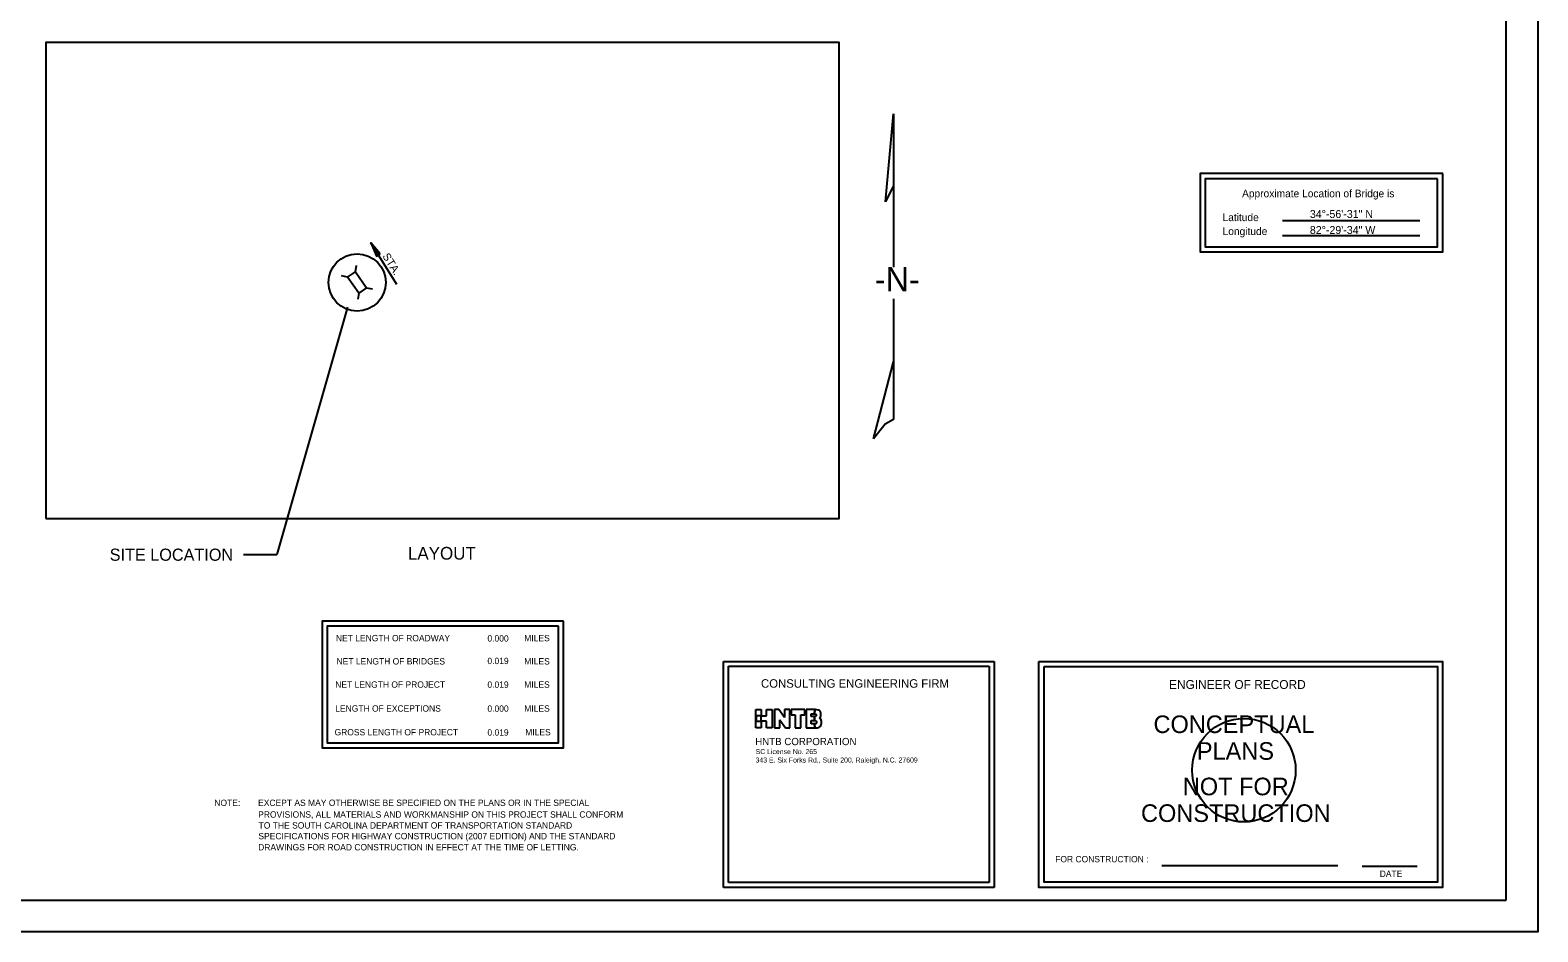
# Model space of a CAD drawing. Extents: x -2.83 to 3.9, y -2.5 to 2.32.
# Drawn here: x 1.021 to 3, y -2.5 to -1.316 of the extents above; entities that cross this region are included whole.
import ezdxf

# ---------------------------------------------------------------- set-up
doc = ezdxf.new("R2010")
doc.units = 0
for name, color, linetype in [('BR_AUTO DIMENSION', 7, 'Continuous'), ('BR_BORDER LINES', 7, 'Continuous'), ('BR_DETAILS', 7, 'Continuous'), ('BR_TEXT', 7, 'Continuous'), ('Default', 7, 'Continuous'), ('NoPlot', 7, 'Continuous'), ('V7_1', 7, 'Continuous'), ('V7_23', 7, 'Continuous')]:
    doc.layers.add(name, color=color, linetype=linetype)

msp = doc.modelspace()

# ---------------------------------------------------------------- linework, layer by layer
at = {"layer": 'BR_AUTO DIMENSION'}
for p, q in [((2.1436, -1.5418), (2.1542, -1.4259)), ((2.1542, -1.4259), (2.1542, -1.5203)), ((2.1542, -1.5203), (2.1436, -1.5418)), ((2.1542, -1.5203), (2.1542, -1.5857)), ((2.1542, -1.5857), (2.1542, -1.6274)), ((1.4372, -1.6798), (1.3443, -2.0048)), ((2.1542, -1.6691), (2.1542, -1.7516)), ((2.1279, -1.8526), (2.1542, -1.7516)), ((2.1542, -1.7516), (2.1542, -1.7641)), ((2.1542, -1.7641), (2.1542, -1.8273)), ((1.3005, -2.0048), (1.3443, -2.0048)), ((1.931, -2.1449), (2.286, -2.1449)), ((1.931, -2.4416), (1.931, -2.1449)), ((1.9373, -2.1513), (2.2796, -2.1513)), ((1.9373, -2.4352), (1.9373, -2.1513)), ((2.2796, -2.1513), (2.2796, -2.4352)), ((2.286, -2.1449), (2.286, -2.4416)), ((2.286, -2.4416), (1.931, -2.4416)), ((2.2796, -2.4352), (1.9373, -2.4352))]:
    msp.add_line(p, q, dxfattribs=at)
msp.add_lwpolyline([(2.1542, -1.8273), (2.1429, -1.8334), (2.1279, -1.8526)], dxfattribs=at)
msp.add_circle((1.4498, -1.6474), 0.0376, dxfattribs=at)
at = {"layer": 'BR_BORDER LINES'}
for p, q in [((2.9583, -2.4582), (2.9583, -0.7082)), ((2.9583, -1.3928), (2.9583, -0.8053)), ((0.1667, -2.4582), (2.9583, -2.4582))]:
    msp.add_line(p, q, dxfattribs=at)
msp.add_lwpolyline([(1.0411, -1.9573), (2.0828, -1.9573), (2.0828, -1.3323), (1.0411, -1.3323)], close=True, dxfattribs=at)
at = {"layer": 'BR_DETAILS'}
for p, q in [((2.6648, -1.5663), (2.8451, -1.5663)), ((2.6648, -1.5856), (2.8451, -1.5856)), ((2.5063, -2.4129), (2.7373, -2.4129)), ((2.7692, -2.4138), (2.8416, -2.4138))]:
    msp.add_line(p, q, dxfattribs=at)
for points in [[(2.8751, -1.5046), (2.5566, -1.5046), (2.5566, -1.6073), (2.8751, -1.6073)], [(2.8684, -1.5113), (2.5633, -1.5113), (2.5633, -1.6006), (2.8684, -1.6006)], [(2.345, -2.1449), (2.875, -2.1449), (2.875, -2.4416), (2.345, -2.4416)], [(2.3517, -2.1515), (2.8683, -2.1515), (2.8683, -2.4349), (2.3517, -2.4349)]]:
    msp.add_lwpolyline(points, close=True, dxfattribs=at)
at = {"layer": 'BR_TEXT'}
for p, q in [((1.5018, -1.6501), (1.4678, -1.5956)), ((1.4374, -1.6404), (1.4295, -1.6388)), ((1.4475, -1.6334), (1.4488, -1.6253)), ((1.4521, -1.6614), (1.4509, -1.6695)), ((1.4622, -1.6544), (1.4702, -1.656))]:
    msp.add_line(p, q, dxfattribs=at)
for points in [[(1.4801, -1.6099), (1.4678, -1.5956), (1.4753, -1.6129)], [(1.4374, -1.6404), (1.4475, -1.6334), (1.4622, -1.6544), (1.4521, -1.6614)], [(1.7207, -2.0919), (1.4041, -2.0919), (1.4041, -2.2586), (1.7207, -2.2586)], [(1.7141, -2.0986), (1.4107, -2.0986), (1.4107, -2.2519), (1.7141, -2.2519)]]:
    msp.add_lwpolyline(points, close=True, dxfattribs=at)
at = {"layer": 'Default'}
msp.add_line((2.61, -2.2932), (2.61, -2.2932), dxfattribs=at)
at = {"layer": 'NoPlot'}
msp.add_lwpolyline([(0, -0.6667), (3, -0.6667), (3, -2.5), (0, -2.5)], close=True, dxfattribs=at)
msp.add_circle((2.6141, -2.2878), 0.0679, dxfattribs=at)
at = {"layer": 'V7_23'}
for p, q in [((1.9733, -2.2323), (1.9733, -2.2083)), ((1.9733, -2.2083), (1.9804, -2.2083)), ((1.9804, -2.2164), (1.9736, -2.2164)), ((1.9736, -2.2164), (1.9736, -2.2235)), ((1.9804, -2.2083), (1.9804, -2.2164)), ((1.9804, -2.2235), (1.9804, -2.2164)), ((1.9804, -2.2164), (1.9875, -2.2164)), ((1.9875, -2.2164), (1.9875, -2.2083)), ((1.9875, -2.2083), (1.9946, -2.2083)), ((1.9946, -2.2083), (1.9946, -2.2323)), ((2.0037, -2.2083), (1.9978, -2.2083)), ((1.9978, -2.2083), (1.9978, -2.2323)), ((2.0108, -2.2188), (2.0037, -2.2083)), ((2.0178, -2.2083), (2.0108, -2.2083)), ((2.0108, -2.2083), (2.0108, -2.2188)), ((2.0178, -2.2323), (2.0178, -2.2083)), ((2.0198, -2.2083), (2.0198, -2.2153)), ((2.0375, -2.2083), (2.0198, -2.2083)), ((2.0198, -2.2153), (2.0251, -2.2153)), ((2.0251, -2.2153), (2.0251, -2.2323)), ((2.0322, -2.2323), (2.0322, -2.2153)), ((2.0322, -2.2153), (2.0375, -2.2153)), ((2.0375, -2.2153), (2.0375, -2.2083)), ((2.0507, -2.2083), (2.0396, -2.2083)), ((2.0396, -2.2083), (2.0396, -2.2323)), ((2.0461, -2.2172), (2.0461, -2.2137)), ((2.0461, -2.2137), (2.0503, -2.2137)), ((2.0503, -2.2137), (2.0507, -2.2083)), ((2.0507, -2.2083), (2.0503, -2.2137)), ((1.9804, -2.2323), (1.9733, -2.2323)), ((1.9736, -2.2235), (1.9804, -2.2235)), ((1.9875, -2.2235), (1.9804, -2.2235)), ((1.9804, -2.2235), (1.9804, -2.2323)), ((1.9875, -2.2323), (1.9875, -2.2235)), ((1.9946, -2.2323), (1.9875, -2.2323)), ((1.9978, -2.2323), (2.0048, -2.2323)), ((2.0048, -2.2323), (2.0048, -2.2215)), ((2.0048, -2.2215), (2.0121, -2.2323)), ((2.0121, -2.2323), (2.0178, -2.2323)), ((2.0251, -2.2323), (2.0322, -2.2323)), ((2.0396, -2.2323), (2.0506, -2.2323)), ((2.0505, -2.2172), (2.0461, -2.2172)), ((2.0461, -2.227), (2.0461, -2.2225)), ((2.0461, -2.2225), (2.0502, -2.2225)), ((2.0503, -2.227), (2.0461, -2.227)), ((2.0502, -2.2225), (2.0505, -2.2172)), ((2.0505, -2.2172), (2.0502, -2.2225)), ((2.0506, -2.2323), (2.0503, -2.227)), ((2.0503, -2.227), (2.0506, -2.2323))]:
    msp.add_line(p, q, dxfattribs=at)
for points in [[(2.0503, -2.2137), (2.0522, -2.2137), (2.0524, -2.2149), (2.0524, -2.2155), (2.0524, -2.2161), (2.052, -2.2172), (2.0505, -2.2172)], [(2.0568, -2.2194), (2.0582, -2.2182), (2.0588, -2.2165), (2.0588, -2.2153), (2.0588, -2.211), (2.0557, -2.2083), (2.0507, -2.2083), (2.0507, -2.2083), (2.0507, -2.2083), (2.0506, -2.2083)], [(2.0502, -2.2225), (2.0524, -2.2225), (2.0528, -2.2237), (2.0528, -2.2247), (2.0528, -2.2261), (2.0519, -2.227), (2.0503, -2.227)], [(2.0506, -2.2323), (2.0561, -2.2323), (2.0595, -2.2292), (2.0595, -2.2242), (2.0595, -2.2223), (2.0585, -2.2205), (2.0568, -2.2194)]]:
    msp.add_open_spline(points, degree=3, dxfattribs=at)

# ---------------------------------------------------------------- texts
at = {"layer": 'BR_AUTO DIMENSION'}
for s, p in [('34°-56\'-31" N', (2.7007, -1.5628)), ('82°-29\'-34" W', (2.7007, -1.5838))]:
    msp.add_text(s, height=0.010417, dxfattribs=at).set_placement(p)
msp.add_text('-N-', height=0.03184, rotation=360, dxfattribs=at).set_placement((2.1294, -1.6591))
at = {"layer": 'BR_DETAILS'}
for s, height, p in [('Approximate Location of Bridge is', 0.01, (2.6117, -1.5356)), ('Latitude', 0.01, (2.586, -1.5669)), ('Longitude', 0.01, (2.5861, -1.5852)), ('LAYOUT', 0.01667, (1.5165, -2.0113)), ('ENGINEER OF RECORD', 0.011667, (2.5158, -2.1811)), ('NOTE:', 0.00833, (1.2624, -2.3348)), ('EXCEPT AS MAY OTHERWISE BE SPECIFIED ON THE PLANS OR IN THE SPECIAL ', 0.008334, (1.3198, -2.3347)), ('PROVISIONS, ALL MATERIALS AND WORKMANSHIP ON THIS PROJECT SHALL CONFORM ', 0.008334, (1.3199, -2.3501)), ('TO THE SOUTH CAROLINA DEPARTMENT OF TRANSPORTATION STANDARD ', 0.008334, (1.3205, -2.3644)), ('SPECIFICATIONS FOR HIGHWAY CONSTRUCTION (2007 EDITION) AND THE STANDARD', 0.008334, (1.3202, -2.3785)), ('DRAWINGS FOR ROAD CONSTRUCTION IN EFFECT AT THE TIME OF LETTING.', 0.008334, (1.3199, -2.3931)), ('FOR CONSTRUCTION :', 0.008333, (2.3663, -2.4087)), ('DATE', 0.00833, (2.7924, -2.4279))]:
    msp.add_text(s, height=height, dxfattribs=at).set_placement(p)
for s, height, p in [('CONCEPTUAL', 0.02311, (2.4954, -2.239)), ('PLANS', 0.02311, (2.5523, -2.2741)), ('NOT FOR', 0.02311, (2.5339, -2.3207)), ('CONSTRUCTION', 0.023108, (2.479, -2.3557))]:
    msp.add_text(s, height=height, rotation=360, dxfattribs=at).set_placement(p)
at = {"layer": 'BR_TEXT'}
for s, height, rotation, p in [('STA.', 0.01042, 301.9956, (1.4826, -1.6128)), ('SITE LOCATION ', 0.015922, 360, (1.125, -2.0128)), ('CONSULTING ENGINEERING FIRM', 0.011145, 0, (1.9801, -2.1795))]:
    msp.add_text(s, height=height, rotation=rotation, dxfattribs=at).set_placement(p)
for s, height, p in [('NET LENGTH OF ROADWAY', 0.008333, (1.422, -2.1185)), ('0.000', 0.00833, (1.6209, -2.1189)), ('MILES', 0.00833, (1.6693, -2.1185)), ('NET LENGTH OF BRIDGES', 0.008333, (1.4228, -2.149)), ('0.019', 0.00833, (1.6209, -2.1485)), ('MILES', 0.00833, (1.6693, -2.149)), ('NET LENGTH OF PROJECT', 0.008333, (1.4211, -2.1795)), ('0.019', 0.00833, (1.6209, -2.1796)), ('MILES', 0.00833, (1.6693, -2.1795)), ('LENGTH OF EXCEPTIONS', 0.008333, (1.4211, -2.2109)), ('0.000', 0.00833, (1.6209, -2.2111)), ('MILES', 0.00833, (1.6693, -2.2109)), ('GROSS LENGTH OF PROJECT', 0.008333, (1.4202, -2.2421)), ('0.019', 0.00833, (1.6209, -2.2424)), ('MILES', 0.00833, (1.6706, -2.2421)), ('343 E. Six Forks Rd., Suite 200, Raleigh, N.C. 27609', 0.006558, (1.9729, -2.2777)), ('SC License No. 265', 0.006558, (1.973, -2.2666))]:
    msp.add_text(s, height=height, dxfattribs=at).set_placement(p)
at = {"layer": 'V7_1'}
msp.add_text('HNTB CORPORATION', height=0.009516, dxfattribs=at).set_placement((1.9725, -2.2549))

doc.saveas('drawing.dxf')
